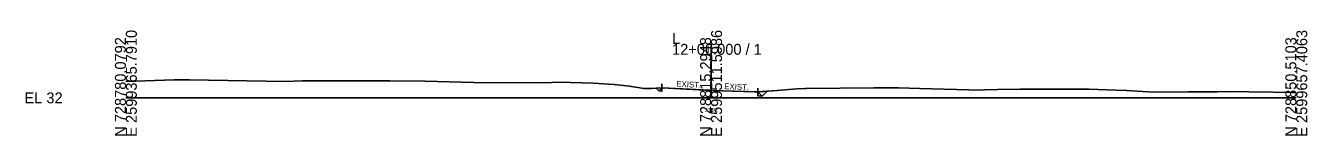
# Model space of a CAD drawing. Extents: x -26 to 3303, y -10 to 9555.
# Drawn here: x -25.7 to 302.8, y 3990.3 to 4017.3 of the extents above; entities that cross this region are included whole.
import ezdxf

# ---------------------------------------------------------------- set-up
doc = ezdxf.new("R2010")
doc.units = 0
for name, color, linetype in [('Exist Cross Section Cell', 7, 'Continuous'), ('Exist XS Center Line Elevation Label', 7, 'Continuous'), ('Exist XS Ground Line', 7, 'Continuous'), ('Prop XS Dump Level', 7, 'Continuous'), ('Prop XS Earthwork Shape', 7, 'Continuous'), ('Prop XS EOT Tick Mark', 7, 'Continuous'), ('Prop XS Finish Grade', 7, 'Continuous'), ('Prop XS Finish Grade Earthwork', 7, 'Continuous'), ('Prop XS Finish Grade Pavement', 7, 'Continuous'), ('Prop XS Pvmt Edge Slope', 7, 'Continuous'), ('Prop XS SE Text', 7, 'Continuous'), ('Prop XS Subgrade Earthwork', 7, 'Continuous')]:
    doc.layers.add(name, color=color, linetype=linetype)

msp = doc.modelspace()

# ---------------------------------------------------------------- linework, layer by layer
at = {"layer": 'Exist Cross Section Cell'}
for p, q in [((150, 4000), (150, 4013.89)), ((0, 4000), (150, 4000)), ((150, 4000), (300, 4000))]:
    msp.add_line(p, q, dxfattribs=at)
at = {"layer": 'Exist XS Ground Line'}
for points in [[(0, 4004.21), (12.38, 4004.6), (13.33, 4004.63), (16.34, 4004.61), (40.87, 4004.19), (45.21, 4004.37), (49.3, 4004.37), (50.67, 4004.37), (51.21, 4004.37), (61.15, 4004.34), (67.69, 4004.34), (76.63, 4004.32), (89.22, 4003.96), (106.92, 4003.89), (111.33, 4004.01), (113.93, 4003.93), (119.81, 4003.76), (125.12, 4003.47), (129.06, 4002.97), (132.74, 4002.38), (134.71, 4002.44), (137.42, 4002.57), (142.78, 4002.35), (149.67, 4001.94), (150, 4001.92), (161.13, 4001.55), (162, 4001.52), (162.39, 4001.55), (166.92, 4001.9)], [(166.92, 4001.9), (171.99, 4002.29), (173.99, 4002.44), (174.42, 4002.45), (191.73, 4002.58), (198.13, 4002.6), (203.46, 4002.44), (216.11, 4002.05), (218.49, 4002.02), (220.1, 4002.05), (223.45, 4002.15), (229.18, 4002.27), (235.57, 4002.27), (245.58, 4002.27), (246.91, 4002.25), (253.82, 4001.98), (256.54, 4001.9), (260.62, 4001.63), (262.09, 4001.56), (263.68, 4001.49), (272.34, 4001.54), (278.28, 4001.58), (279.68, 4001.59), (281.72, 4001.6), (294.07, 4001.43), (298.68, 4001.37), (300, 4001.34)]]:
    msp.add_lwpolyline(points, dxfattribs=at)
at = {"layer": 'Prop XS Dump Level'}
for p in [(137.42, 4002.57), (162, 4001.52)]:
    msp.add_line(p, (150, 4001.92), dxfattribs=at)
at = {"layer": 'Prop XS Earthwork Shape'}
for points in [[(135.9, 4002.51), (132.74, 4002.38), (134.71, 4002.44), (135.91, 4002.5)], [(134.71, 4002.44), (135.91, 4002.5), (135.9, 4002.51), (132.74, 4002.38)], [(136.63, 4001.77), (135.91, 4002.5), (137.42, 4002.57), (137.42, 4001.72)], [(135.91, 4002.5), (137.42, 4002.57), (137.42, 4001.72), (136.63, 4001.77)], [(162, 4000.49), (162, 4001.52), (162.39, 4001.55), (164.34, 4001.69), (163.08, 4000.44)], [(162.39, 4001.55), (164.34, 4001.69), (163.08, 4000.44), (162, 4000.49), (162, 4001.52)]]:
    msp.add_lwpolyline(points, close=True, dxfattribs=at)
at = {"layer": 'Prop XS EOT Tick Mark'}
for p, q in [((137.42, 4002.57), (137.42, 4003.57)), ((162, 4001.52), (162, 4002.52))]:
    msp.add_line(p, q, dxfattribs=at)
at = {"layer": 'Prop XS Finish Grade'}
for p, q in [((137.42, 4002.57), (135.9, 4002.51)), ((162, 4001.52), (164.34, 4001.69))]:
    msp.add_line(p, q, dxfattribs=at)
at = {"layer": 'Prop XS Finish Grade Earthwork'}
for p, q in [((135.9, 4002.51), (132.74, 4002.38)), ((164.34, 4001.69), (166.92, 4001.9))]:
    msp.add_line(p, q, dxfattribs=at)
at = {"layer": 'Prop XS Finish Grade Pavement'}
for p, q in [((137.42, 4002.57), (150, 4001.92)), ((150, 4001.92), (162, 4001.52))]:
    msp.add_line(p, q, dxfattribs=at)
at = {"layer": 'Prop XS Pvmt Edge Slope'}
for p, q in [((136.63, 4001.77), (135.9, 4002.51)), ((137.42, 4002.57), (136.63, 4001.77)), ((163.08, 4000.44), (164.34, 4001.69)), ((162, 4001.52), (163.08, 4000.44))]:
    msp.add_line(p, q, dxfattribs=at)
at = {"layer": 'Prop XS Subgrade Earthwork'}
for p, q in [((136.63, 4001.77), (135.9, 4002.51)), ((137.42, 4001.72), (136.63, 4001.77)), ((137.42, 4001.72), (137.42, 4002.57)), ((163.08, 4000.44), (164.34, 4001.69)), ((162, 4000.49), (162, 4001.52)), ((162, 4000.49), (163.08, 4000.44))]:
    msp.add_line(p, q, dxfattribs=at)

# ---------------------------------------------------------------- texts
at = {"layer": 'Exist Cross Section Cell'}
for s, p in [('N 728780.0792', (0, 3990)), ('E 2599365.7910', (2.8, 3990)), ('N 728815.2948', (150, 3990)), ('E 2599511.5986', (152.8, 3990)), ('N 728850.5103', (300, 3990)), ('E 2599657.4063', (302.8, 3990))]:
    msp.add_text(s, height=2.8, rotation=90, dxfattribs=at).set_placement(p)
for s, p in [('L', (140, 4013.89)), ('12+00.000 / 1', (140, 4011.09)), ('EL 32', (-26, 3998.6))]:
    msp.add_text(s, height=2.8, dxfattribs=at).set_placement(p)
at = {"layer": 'Exist XS Center Line Elevation Label'}
msp.add_text('33.92', height=1, dxfattribs=at).set_placement((148.29, 3996.42))
at = {"layer": 'Prop XS Dump Level'}
for p in [(137.42, 4002.27), (162, 4001.22)]:
    msp.add_text('Eop', height=0.3, dxfattribs=at).set_placement(p)
at = {"layer": 'Prop XS SE Text'}
for p in [(141.06, 4002.87), (153.35, 4002.26)]:
    msp.add_text('EXIST.', height=1.5, rotation=357.1376, dxfattribs=at).set_placement(p)

doc.saveas('drawing.dxf')
